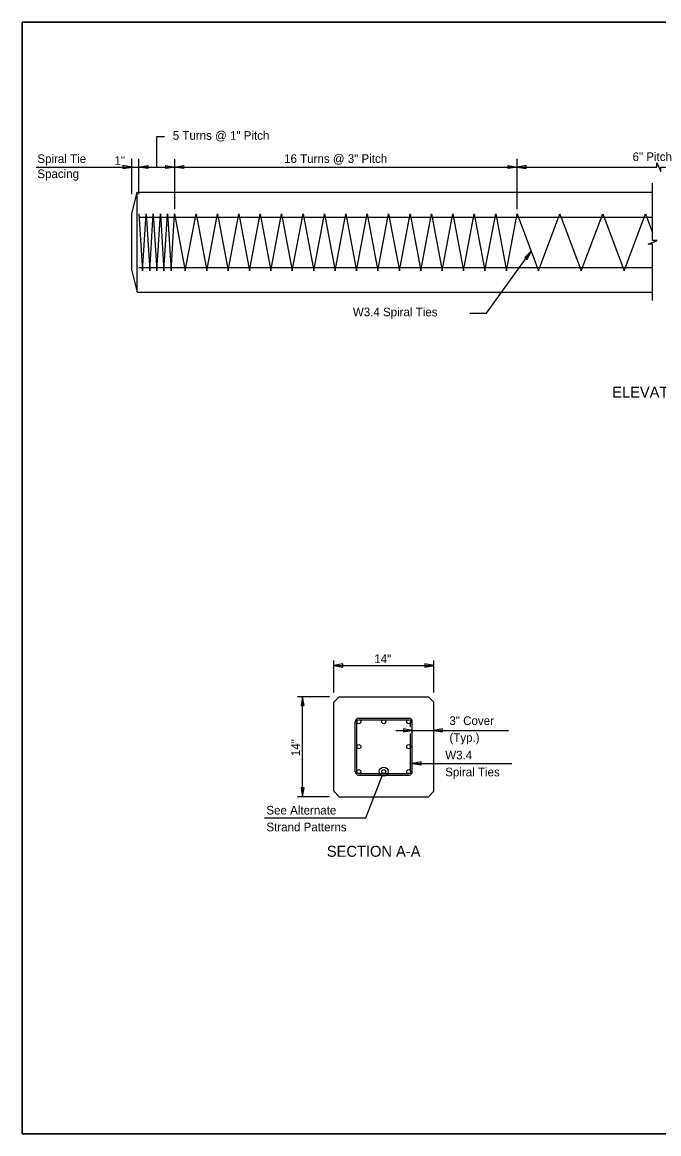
# Model space of a CAD drawing. Extents: x 0 to 20.5, y 0 to 13.
# Drawn here: x 0 to 7.44, y 0 to 12.97 of the extents above; entities that cross this region are included whole.
import ezdxf

# ---------------------------------------------------------------- set-up
doc = ezdxf.new("R2010")
doc.units = 0
for name, color, linetype in [('Dimension', 7, 'Continuous'), ('Miscellaneous1', 7, 'Continuous'), ('PileConc', 7, 'Continuous'), ('Rebar', 7, 'Continuous'), ('TextStructures', 7, 'Continuous')]:
    doc.layers.add(name, color=color, linetype=linetype)

msp = doc.modelspace()

# ---------------------------------------------------------------- linework, layer by layer
at = {"layer": 'Dimension'}
for p, q in [((1.572, 11.281), (1.572, 11.638)), ((1.572, 11.638), (1.661, 11.638)), ((1.281, 10.965), (1.281, 11.38)), ((1.364, 10.965), (1.364, 11.38)), ((1.781, 10.793), (1.781, 11.38)), ((5.781, 10.793), (5.781, 11.38)), ((0.164, 11.281), (1.281, 11.281)), ((1.281, 11.281), (1.364, 11.281)), ((1.364, 11.281), (1.781, 11.281)), ((1.781, 11.281), (5.781, 11.281)), ((5.423, 9.576), (5.944, 10.3)), ((5.227, 9.576), (5.423, 9.576)), ((3.639, 5.15), (3.639, 5.522)), ((3.639, 5.465), (4.806, 5.465)), ((4.806, 5.15), (4.806, 5.522)), ((3.59, 5.101), (3.217, 5.101)), ((3.275, 3.934), (3.275, 5.101)), ((4.364, 4.708), (4.556, 4.708)), ((4.556, 4.708), (4.806, 4.708)), ((4.806, 4.708), (5.68, 4.708)), ((4.556, 4.322), (5.72, 4.322)), ((4.014, 3.687), (4.204, 4.177)), ((3.59, 3.934), (3.217, 3.934)), ((2.831, 3.687), (4.014, 3.687))]:
    msp.add_line(p, q, dxfattribs=at)
for points in [[(0, 0), (20.525, 0), (20.525, 12.973), (0, 12.973)], [(1.281, 11.281), (1.177, 11.299), (1.177, 11.264)], [(1.364, 11.281), (1.468, 11.299), (1.468, 11.264)], [(1.781, 11.281), (1.677, 11.264), (1.677, 11.299)], [(1.781, 11.281), (1.885, 11.299), (1.885, 11.264)], [(5.781, 11.281), (5.677, 11.264), (5.677, 11.299)], [(5.781, 11.281), (5.885, 11.264), (5.885, 11.299)], [(5.944, 10.3), (5.869, 10.226), (5.898, 10.205)], [(3.639, 5.465), (3.743, 5.447), (3.743, 5.483)], [(4.806, 5.465), (4.702, 5.483), (4.702, 5.447)], [(3.275, 5.101), (3.258, 4.997), (3.293, 4.997)], [(4.556, 4.708), (4.452, 4.726), (4.452, 4.69)], [(4.806, 4.708), (4.91, 4.69), (4.91, 4.726)], [(4.556, 4.322), (4.66, 4.305), (4.66, 4.34)], [(3.275, 3.934), (3.293, 4.038), (3.258, 4.038)]]:
    msp.add_lwpolyline(points, close=True, dxfattribs=at)
for points in [[(5.781, 11.281), (7.413, 11.281), (7.413, 11.333), (7.435, 11.281), (7.458, 11.23), (7.458, 11.281), (9.09, 11.281)], [(7.363, 9.724), (7.363, 10.382), (7.311, 10.382), (7.363, 10.404), (7.415, 10.427), (7.363, 10.427), (7.363, 11.094)]]:
    msp.add_lwpolyline(points, dxfattribs=at)
msp.add_circle((4.223, 4.227), 0.0528, dxfattribs=at)
at = {"layer": 'Miscellaneous1'}
msp.add_lwpolyline([(0, 12.973), (20.525, 12.973), (20.525, 0), (0, 0)], close=True, dxfattribs=at)
at = {"layer": 'PileConc'}
for p, q in [((1.281, 10.738), (1.343, 10.988)), ((1.343, 10.988), (7.363, 10.988)), ((1.343, 9.821), (1.343, 10.988)), ((1.281, 10.071), (1.281, 10.738)), ((1.281, 10.071), (1.343, 9.821)), ((1.343, 9.821), (7.363, 9.821)), ((3.702, 5.101), (3.639, 5.039)), ((3.702, 5.101), (4.744, 5.101)), ((4.806, 5.039), (4.744, 5.101)), ((3.639, 3.997), (3.639, 5.039)), ((4.806, 3.997), (4.806, 5.039)), ((3.639, 3.997), (3.702, 3.934)), ((3.702, 3.934), (4.744, 3.934)), ((4.744, 3.934), (4.806, 3.997))]:
    msp.add_line(p, q, dxfattribs=at)
at = {"layer": 'Rebar'}
for p, q in [((1.364, 10.738), (1.406, 10.071)), ((1.364, 10.698), (7.363, 10.698)), ((1.406, 10.071), (1.447, 10.738)), ((1.447, 10.738), (1.489, 10.071)), ((1.489, 10.071), (1.531, 10.738)), ((1.531, 10.738), (1.572, 10.071)), ((1.572, 10.071), (1.614, 10.738)), ((1.614, 10.738), (1.656, 10.071)), ((1.656, 10.071), (1.697, 10.738)), ((1.697, 10.738), (1.739, 10.071)), ((1.739, 10.071), (1.78, 10.738)), ((1.78, 10.738), (1.905, 10.071)), ((1.905, 10.071), (2.03, 10.738)), ((2.03, 10.738), (2.155, 10.071)), ((2.155, 10.071), (2.28, 10.738)), ((2.28, 10.738), (2.405, 10.071)), ((2.405, 10.071), (2.53, 10.738)), ((2.53, 10.738), (2.655, 10.071)), ((2.655, 10.071), (2.78, 10.738)), ((2.78, 10.738), (2.905, 10.071)), ((2.905, 10.071), (3.03, 10.738)), ((3.03, 10.738), (3.155, 10.071)), ((3.155, 10.071), (3.28, 10.738)), ((3.28, 10.738), (3.405, 10.071)), ((3.405, 10.071), (3.53, 10.738)), ((3.53, 10.738), (3.655, 10.071)), ((3.655, 10.071), (3.78, 10.738)), ((3.78, 10.738), (3.905, 10.071)), ((3.905, 10.071), (4.03, 10.738)), ((4.03, 10.738), (4.155, 10.071)), ((4.155, 10.071), (4.28, 10.738)), ((4.28, 10.738), (4.405, 10.071)), ((4.405, 10.071), (4.53, 10.738)), ((4.53, 10.738), (4.655, 10.071)), ((4.655, 10.071), (4.78, 10.738)), ((4.78, 10.738), (4.905, 10.071)), ((4.905, 10.071), (5.03, 10.738)), ((5.03, 10.738), (5.155, 10.071)), ((5.155, 10.071), (5.28, 10.738)), ((5.28, 10.738), (5.405, 10.071)), ((5.405, 10.071), (5.53, 10.738)), ((5.53, 10.738), (5.655, 10.071)), ((5.655, 10.071), (5.78, 10.738)), ((5.78, 10.738), (6.03, 10.071)), ((6.03, 10.071), (6.28, 10.738)), ((6.28, 10.738), (6.53, 10.071)), ((6.53, 10.071), (6.78, 10.738)), ((6.78, 10.738), (7.03, 10.071)), ((7.03, 10.071), (7.28, 10.738)), ((7.28, 10.738), (7.363, 10.517)), ((1.364, 10.11), (7.363, 10.11)), ((3.889, 4.226), (3.889, 4.81)), ((3.908, 4.227), (3.908, 4.808)), ((3.932, 4.851), (4.519, 4.851)), ((3.932, 4.832), (4.514, 4.832)), ((4.537, 4.744), (4.537, 4.808)), ((4.556, 4.226), (4.556, 4.81)), ((4.537, 4.227), (4.537, 4.672)), ((3.932, 4.203), (4.514, 4.203)), ((3.932, 4.184), (4.514, 4.184))]:
    msp.add_line(p, q, dxfattribs=at)
for centre in [(3.932, 4.809), (4.223, 4.809), (4.514, 4.809), (3.932, 4.518), (4.514, 4.518), (3.932, 4.227), (4.223, 4.227), (4.514, 4.227)]:
    msp.add_circle(centre, 0.0234, dxfattribs=at)
for centre, start, end in [((3.932, 4.809), 96.4003, 181.2723), ((4.514, 4.809), 358.7277, 83.5997), ((3.932, 4.227), 178.7277, 263.5997), ((4.514, 4.227), 276.4003, 1.2723)]:
    msp.add_arc(centre, 0.0423, start, end, dxfattribs=at)

# ---------------------------------------------------------------- texts
at = {"layer": 'Dimension'}
for s, p in [('Spiral Tie', (0.177, 11.33)), ('Spacing', (0.177, 11.154)), ('3" Cover', (4.99, 4.771)), ('(Typ.)', (4.99, 4.574)), ('W3.4 ', (4.941, 4.369)), ('Spiral Ties', (4.941, 4.172)), ('See Alternate', (2.852, 3.726)), ('Strand Patterns', (2.852, 3.53))]:
    msp.add_text(s, height=0.1008, dxfattribs=at).set_placement(p)
at = {"layer": 'TextStructures'}
for s, height, p in [('5 Turns @ 1" Pitch', 0.1008, (1.758, 11.601)), ('16 Turns @ 3" Pitch ', 0.1008, (3.059, 11.331)), ('6" Pitch', 0.1008, (7.129, 11.353)), ('1"', 0.1008, (1.078, 11.309)), ('W3.4 Spiral Ties', 0.1008, (3.862, 9.541)), ('ELEVATION', 0.128, (6.891, 8.592)), ('14"', 0.1008, (4.112, 5.493)), ('SECTION A-A', 0.128, (3.558, 3.233))]:
    msp.add_text(s, height=height, dxfattribs=at).set_placement(p)
msp.add_text('14"', height=0.1008, rotation=90, dxfattribs=at).set_placement((3.243, 4.407))

doc.saveas('drawing.dxf')
